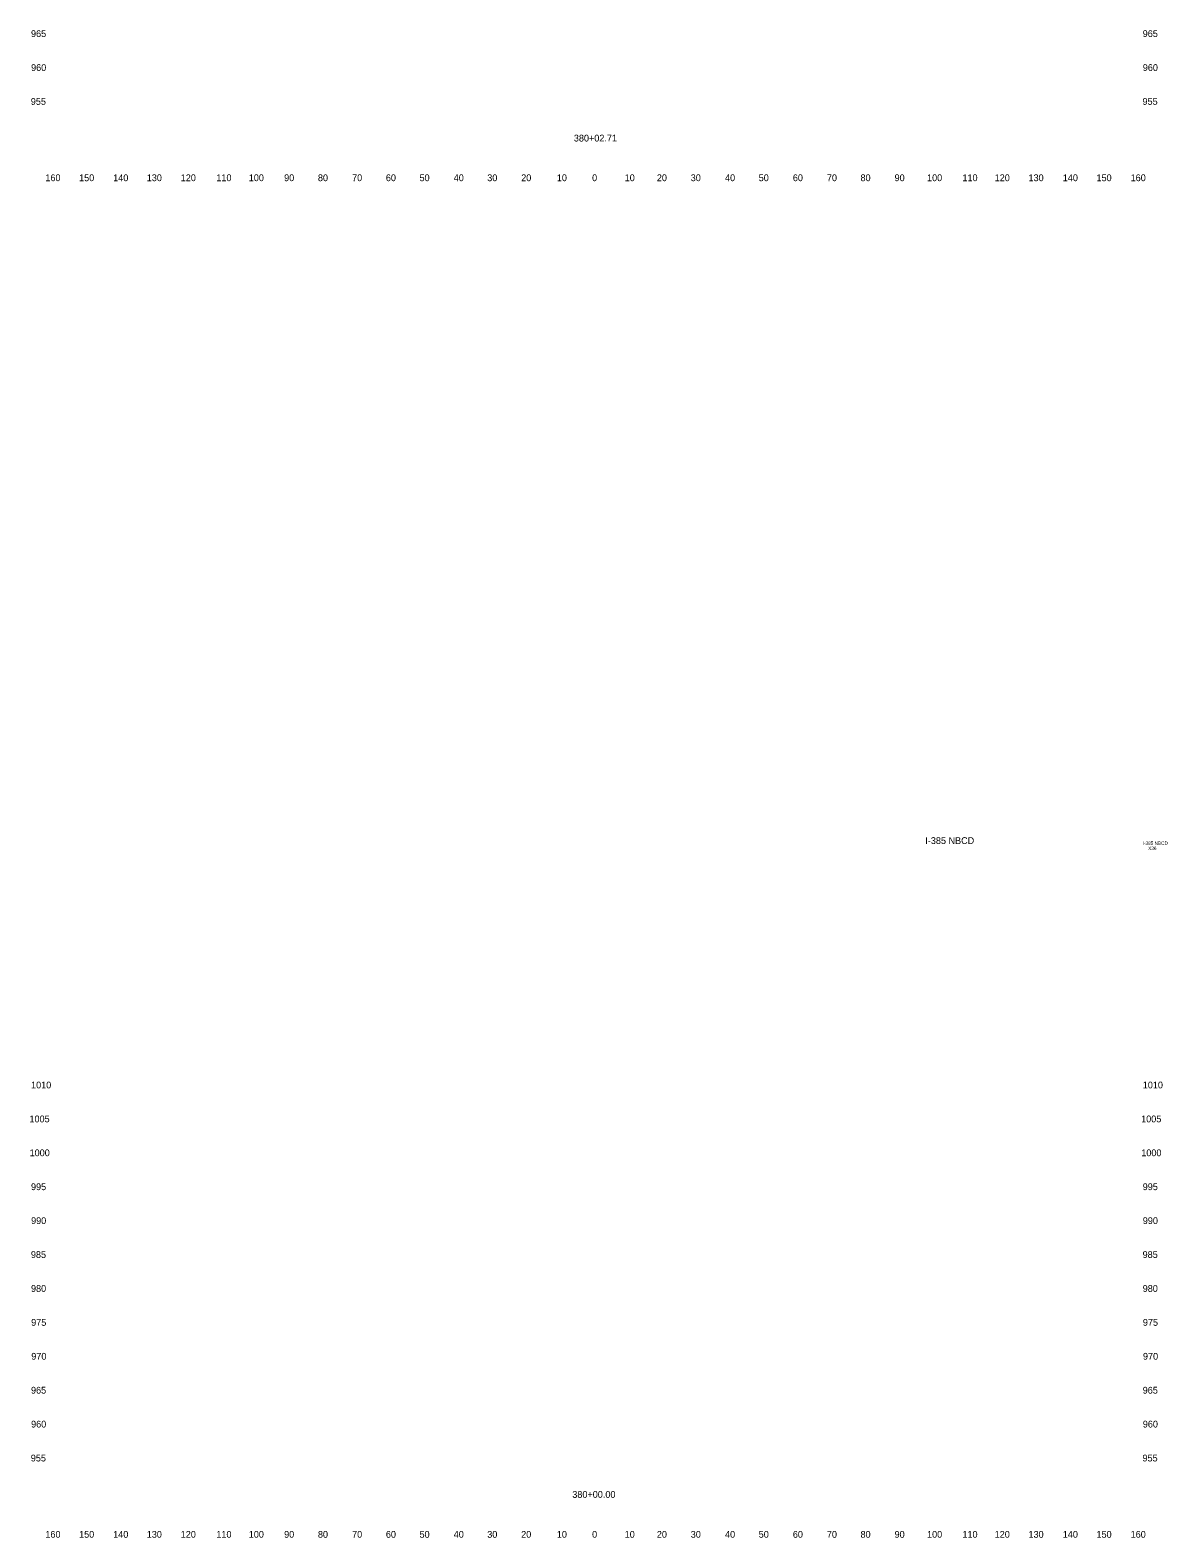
# Model space of a CAD drawing. Extents: x 4994 to 7391, y 4997 to 8804.
# Drawn here: x 6538.6 to 6873.8, y 6997.5 to 7442 of the extents above; entities that cross this region are included whole.
import ezdxf

# ---------------------------------------------------------------- set-up
doc = ezdxf.new("R2010")
doc.units = 0
for name, color, linetype in [('RD_SHT_ID', 7, 'Continuous'), ('RD_XS_TX_Offset', 7, 'Continuous'), ('RD_XS_TX_Station', 7, 'Continuous')]:
    doc.layers.add(name, color=color, linetype=linetype)

msp = doc.modelspace()

# ---------------------------------------------------------------- texts
at = {"layer": 'RD_SHT_ID'}
for s, height, p in [('I-385 NBCD', 2, (6802.56, 7202.06)), ('I-385 NBCD', 1, (6866.63, 7201.8)), ('X36', 1, (6868.26, 7200.3))]:
    msp.add_text(s, height=height, dxfattribs=at).set_placement(p)
at = {"layer": 'RD_XS_TX_Offset'}
for s, p in [('965', (6538.86, 7440)), ('965', (6866.66, 7440)), ('960', (6538.89, 7430)), ('960', (6866.69, 7430)), ('955', (6538.8, 7420)), ('955', (6866.6, 7420)), ('160', (6543.1, 7397.5)), ('150', (6553.04, 7397.5)), ('140', (6563.1, 7397.5)), ('130', (6572.99, 7397.5)), ('120', (6583.01, 7397.5)), ('110', (6593.51, 7397.5)), ('100', (6603.07, 7397.5)), ('90', (6613.5, 7397.5)), ('80', (6623.46, 7397.5)), ('70', (6633.54, 7397.5)), ('60', (6643.5, 7397.5)), ('50', (6653.43, 7397.5)), ('40', (6663.5, 7397.5)), ('30', (6673.39, 7397.5)), ('20', (6683.4, 7397.5)), ('10', (6693.91, 7397.5)), ('0', (6704.3, 7397.5)), ('0', (6704.3, 7397.5)), ('10', (6713.91, 7397.5)), ('20', (6723.4, 7397.5)), ('30', (6733.39, 7397.5)), ('40', (6743.5, 7397.5)), ('50', (6753.43, 7397.5)), ('60', (6763.5, 7397.5)), ('70', (6773.54, 7397.5)), ('80', (6783.46, 7397.5)), ('90', (6793.5, 7397.5)), ('100', (6803.07, 7397.5)), ('110', (6813.51, 7397.5)), ('120', (6823.01, 7397.5)), ('130', (6832.99, 7397.5)), ('140', (6843.1, 7397.5)), ('150', (6853.04, 7397.5)), ('160', (6863.1, 7397.5)), ('1010', (6538.88, 7130)), ('1010', (6866.68, 7130)), ('1005', (6538.4, 7120)), ('1005', (6866.2, 7120)), ('1000', (6538.44, 7110)), ('1000', (6866.24, 7110)), ('995', (6538.86, 7100)), ('995', (6866.66, 7100)), ('990', (6538.89, 7090)), ('990', (6866.69, 7090)), ('985', (6538.83, 7080)), ('985', (6866.63, 7080)), ('980', (6538.86, 7070)), ('980', (6866.66, 7070)), ('975', (6538.91, 7060)), ('975', (6866.71, 7060)), ('970', (6538.94, 7050)), ('970', (6866.74, 7050)), ('965', (6538.86, 7040)), ('965', (6866.66, 7040)), ('960', (6538.89, 7030)), ('960', (6866.69, 7030)), ('955', (6538.8, 7020)), ('955', (6866.6, 7020)), ('160', (6543.1, 6997.5)), ('150', (6553.04, 6997.5)), ('140', (6563.1, 6997.5)), ('130', (6572.99, 6997.5)), ('120', (6583.01, 6997.5)), ('110', (6593.51, 6997.5)), ('100', (6603.07, 6997.5)), ('90', (6613.5, 6997.5)), ('80', (6623.46, 6997.5)), ('70', (6633.54, 6997.5)), ('60', (6643.5, 6997.5)), ('50', (6653.43, 6997.5)), ('40', (6663.5, 6997.5)), ('30', (6673.39, 6997.5)), ('20', (6683.4, 6997.5)), ('10', (6693.91, 6997.5)), ('0', (6704.3, 6997.5)), ('0', (6704.3, 6997.5)), ('10', (6713.91, 6997.5)), ('20', (6723.4, 6997.5)), ('30', (6733.39, 6997.5)), ('40', (6743.5, 6997.5)), ('50', (6753.43, 6997.5)), ('60', (6763.5, 6997.5)), ('70', (6773.54, 6997.5)), ('80', (6783.46, 6997.5)), ('90', (6793.5, 6997.5)), ('100', (6803.07, 6997.5)), ('110', (6813.51, 6997.5)), ('120', (6823.01, 6997.5)), ('130', (6832.99, 6997.5)), ('140', (6843.1, 6997.5)), ('150', (6853.04, 6997.5)), ('160', (6863.1, 6997.5))]:
    msp.add_text(s, height=2, dxfattribs=at).set_placement(p)
at = {"layer": 'RD_XS_TX_Station'}
for s, p in [('380+02.71', (6698.93, 7409.2)), ('380+00.00', (6698.47, 7009.27))]:
    msp.add_text(s, height=2, dxfattribs=at).set_placement(p)

doc.saveas('drawing.dxf')
